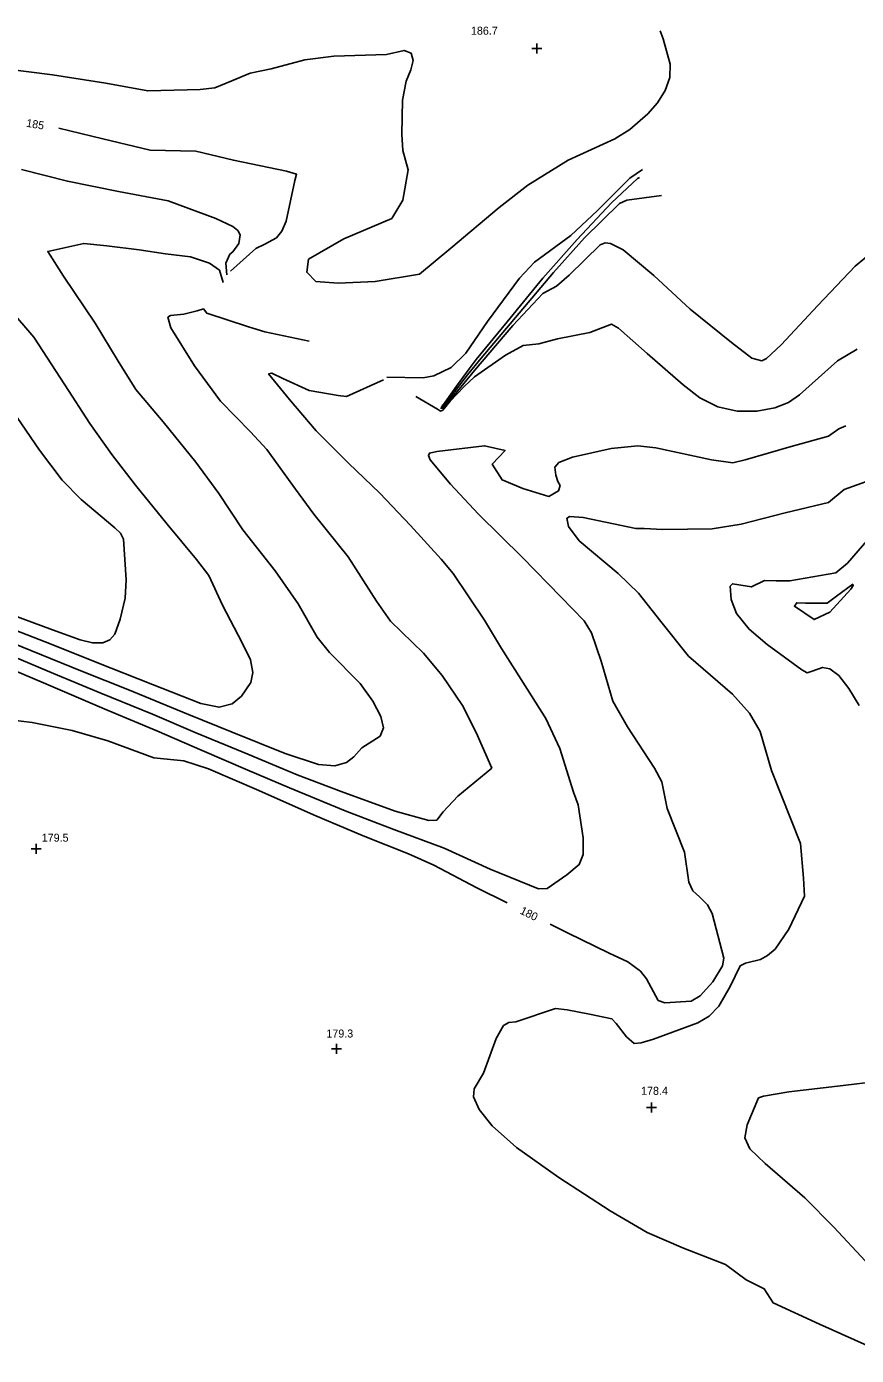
# Model space of a CAD drawing. Extents: x 1467615 to 2003689, y 770235 to 1108726.
# Drawn here: x 1995497.6 to 1995704.8, y 776648.4 to 776980.5 of the extents above; entities that cross this region are included whole.
import ezdxf

# ---------------------------------------------------------------- set-up
doc = ezdxf.new("R2010")
doc.units = 0
for name, color, linetype in [('RD_DTM_Major1', 7, 'Continuous'), ('RD_DTM_Major1_Lbl', 7, 'Continuous'), ('RD_DTM_Minor1', 7, 'Continuous'), ('RD_DTM_Spot_Elev', 7, 'Continuous')]:
    doc.layers.add(name, color=color, linetype=linetype)

msp = doc.modelspace()

# ---------------------------------------------------------------- linework, layer by layer
at = {"layer": 'RD_DTM_Major1'}
for points in [[(1995505.62, 776955.03), (1995516.64, 776952.44), (1995528.45, 776949.54), (1995539.83, 776949.31), (1995549.23, 776947.05), (1995562.51, 776944.31), (1995565.01, 776943.54), (1995564.56, 776941.97), (1995562.4, 776931.84), (1995561.34, 776929.34), (1995560.01, 776927.68), (1995557.09, 776926.11), (1995554.83, 776925.01), (1995548.53, 776919.38)], [(1995587.54, 776892.89), (1995596.57, 776892.69), (1995599.25, 776893.15), (1995603.56, 776895.3), (1995607.22, 776898.86), (1995612.71, 776906.79), (1995620.69, 776917.61), (1995624.37, 776921.59), (1995633.48, 776928.28), (1995640.15, 776934.53), (1995648.22, 776942.59), (1995651.36, 776944.75)], [(1995491.5, 776834.36), (1995504.07, 776829.72), (1995511, 776827.24), (1995514.08, 776826.51), (1995516.6, 776826.45), (1995518.41, 776827.24), (1995519.62, 776828.67), (1995520.98, 776832.36), (1995522.19, 776837.67), (1995522.44, 776842.21), (1995521.79, 776852.42), (1995521.05, 776853.86), (1995519.63, 776855.21), (1995511.26, 776862.3), (1995506.52, 776867.11), (1995500.84, 776874.64), (1995492.92, 776886.19)], [(1995628.33, 776756.19), (1995632.67, 776754.04), (1995643.07, 776748.94), (1995647.72, 776746.78), (1995650.86, 776744.41), (1995652.35, 776742.56), (1995655.29, 776737.13), (1995656.96, 776736.52), (1995663.55, 776736.92), (1995665.73, 776738.32), (1995668.9, 776741.82), (1995671.36, 776745.75), (1995671.63, 776747.72), (1995668.75, 776758.89), (1995667.62, 776761.04), (1995665.62, 776763.01), (1995663.9, 776764.54), (1995662.9, 776766.7), (1995661.89, 776774.2), (1995657.54, 776785.08), (1995656.23, 776791.74), (1995654.37, 776795.14), (1995647.65, 776805.47), (1995643.94, 776811.92), (1995641.07, 776821.9), (1995638.62, 776828.98), (1995636.77, 776831.95), (1995630.99, 776837.96), (1995621.42, 776847.8), (1995610.46, 776858.63), (1995603.39, 776866.15), (1995598.36, 776872.21), (1995597.92, 776873.3), (1995598.18, 776873.88), (1995600.04, 776874.26), (1995611.92, 776875.73), (1995617.06, 776874.55), (1995613.86, 776871.13), (1995616.34, 776867.19), (1995621.53, 776865.06), (1995628.01, 776863.06), (1995630.42, 776864.44), (1995630.77, 776865.82), (1995630.22, 776866.76), (1995629.75, 776868.34), (1995629.45, 776870.41), (1995630.49, 776871.51), (1995633.92, 776872.83), (1995643.5, 776875.02), (1995650.19, 776875.71), (1995654.7, 776875.19), (1995668.59, 776872.17), (1995673.88, 776871.43), (1995677.01, 776872.22), (1995688.48, 776875.54), (1995697.81, 776878.08), (1995700.36, 776879.91), (1995702.09, 776880.73)], [(1995490.64, 776807.61), (1995498.98, 776806.58), (1995508.95, 776804.55), (1995517.88, 776802), (1995529.33, 776797.78), (1995536.88, 776796.97), (1995543.04, 776794.98), (1995555.57, 776789.56), (1995569.26, 776783.52), (1995581.65, 776778.27), (1995592.92, 776773.74), (1995599.27, 776770.93), (1995610.02, 776765.24), (1995617.58, 776761.51)]]:
    msp.add_lwpolyline(points, dxfattribs=at)
at = {"layer": 'RD_DTM_Minor1'}
for points in [[(1995492.96, 776969.77), (1995504.07, 776968.43), (1995517.38, 776966.31), (1995527.86, 776964.36), (1995540.9, 776964.7), (1995544.57, 776965.11), (1995548.84, 776966.89), (1995553.42, 776968.82), (1995558.64, 776969.89), (1995567.1, 776972.16), (1995574.3, 776973.03), (1995587.42, 776973.48), (1995591.85, 776974.51), (1995593.6, 776973.8), (1995594.13, 776971.95), (1995593.53, 776969.68), (1995592.34, 776966.78), (1995591.49, 776962.1), (1995591.28, 776953.58), (1995591.54, 776949.46), (1995592.88, 776944.67), (1995591.54, 776937.08), (1995588.77, 776932.47), (1995576.77, 776927.39), (1995568, 776922.31), (1995567.54, 776919.08), (1995569.84, 776916.77), (1995575.38, 776916.31), (1995584.62, 776916.77), (1995595.7, 776918.62), (1995603.55, 776925.08), (1995615.55, 776935.24), (1995622.71, 776940.79), (1995632.78, 776947.07), (1995644.46, 776952.37), (1995648.24, 776954.7), (1995652.73, 776958.69), (1995655.1, 776961.42), (1995657.06, 776964.48), (1995658.2, 776967.75), (1995658.28, 776971.07), (1995656.49, 776977.36), (1995655.8, 776979.36)], [(1995496.32, 776944.75), (1995507.81, 776941.79), (1995520.57, 776939.21), (1995532.97, 776936.9), (1995544.83, 776932.48), (1995549.06, 776930.54), (1995550.37, 776929.5), (1995550.95, 776928.38), (1995550.63, 776926.23), (1995549.12, 776924.21), (1995548.32, 776923.58), (1995547.33, 776921.38), (1995547.62, 776918.4)], [(1995601.28, 776885.7), (1995601.59, 776885.95), (1995602.1, 776886.57), (1995604.95, 776890.61), (1995608.1, 776894.95), (1995609.87, 776897.27), (1995617.58, 776906.65), (1995626.51, 776917.62), (1995635.07, 776927.27), (1995643.59, 776936.42), (1995650.13, 776942.47), (1995650.58, 776942.78)], [(1995601.12, 776885.4), (1995601.65, 776885.62), (1995602.13, 776886.16), (1995604.44, 776889.22), (1995607.68, 776893.43), (1995611.1, 776897.62), (1995620.58, 776908.82), (1995629.13, 776919.02), (1995636.92, 776927.67), (1995645.66, 776936.23), (1995647.46, 776937.08), (1995656.09, 776938.24)], [(1995491.52, 776827.48), (1995503.57, 776822.53), (1995511.56, 776819.34), (1995522.86, 776814.83), (1995538.05, 776808.58), (1995548.91, 776804.17), (1995562.15, 776798.83), (1995570.45, 776796.07), (1995574.58, 776795.73), (1995577.51, 776796.59), (1995579.27, 776798.01), (1995581.33, 776800.26), (1995585.9, 776803.17), (1995586.72, 776805.22), (1995586.05, 776808.09), (1995584.06, 776811.94), (1995580.87, 776816.3), (1995573.21, 776824.1), (1995570.17, 776827.91), (1995565.43, 776836.24), (1995559.65, 776844.48), (1995551.6, 776854.71), (1995545.61, 776863.83), (1995539.83, 776871.65), (1995531.7, 776881.73), (1995524.86, 776889.8), (1995520.5, 776896.85), (1995514.73, 776906.31), (1995506.82, 776918.08), (1995502.89, 776924.27), (1995511.87, 776926.28), (1995517.66, 776925.64), (1995525.74, 776924.7), (1995532.28, 776923.69), (1995538.51, 776922.94), (1995543.26, 776921.32), (1995545.77, 776919.55), (1995546.71, 776916.54)], [(1995600.96, 776885.07), (1995601.35, 776885.12), (1995601.68, 776885.27), (1995603.11, 776886.87), (1995606.79, 776891.3), (1995609.39, 776894.52), (1995619.03, 776905.75), (1995626.51, 776913.73), (1995629.86, 776915.59), (1995633.04, 776918.38), (1995640.76, 776925.95), (1995642.04, 776926.38), (1995643.4, 776926.29), (1995646.51, 776924.66), (1995654.19, 776918.24), (1995663.29, 776909.81), (1995673.57, 776901.48), (1995678.66, 776897.58), (1995681.13, 776896.92), (1995682.35, 776897.48), (1995685.97, 776900.9), (1995695.17, 776910.77), (1995704.49, 776920.57), (1995711.72, 776926.6)], [(1995491.74, 776830.78), (1995503.76, 776826.11), (1995515.18, 776821.58), (1995529.07, 776816.06), (1995541.14, 776811.29), (1995545.65, 776810.38), (1995548.96, 776811.2), (1995551.23, 776813.15), (1995553.55, 776816.56), (1995554.08, 776819.1), (1995553.47, 776822.22), (1995551.45, 776826.51), (1995546.48, 776835.88), (1995543.14, 776843.31), (1995540.06, 776847.32), (1995532.73, 776856.11), (1995524.78, 776865.87), (1995518.88, 776873.53), (1995513.43, 776881.32), (1995507.13, 776890.98), (1995499.41, 776902.88), (1995493.3, 776909.92)], [(1995494.68, 776822.86), (1995504.31, 776818.8), (1995516.17, 776813.88), (1995529.05, 776808.65), (1995539.73, 776804.08), (1995552.83, 776798.65), (1995565.19, 776793.49), (1995576.11, 776789.3), (1995589.6, 776784.44), (1995598.06, 776782.11), (1995600, 776782.18), (1995601.61, 776784.29), (1995605.23, 776788.13), (1995613.73, 776795.2), (1995609.85, 776804.07), (1995606.39, 776810.82), (1995601.31, 776818.35), (1995596.7, 776823.86), (1995588.44, 776831.89), (1995584.99, 776836.85), (1995577.89, 776847.94), (1995569.32, 776858.66), (1995564.71, 776864.9), (1995557.55, 776874.8), (1995553.52, 776879.21), (1995546.03, 776886.83), (1995539.55, 776895.66), (1995533.62, 776905.22), (1995532.87, 776907.81), (1995533.57, 776908.3), (1995536.88, 776908.63), (1995540.17, 776909.47), (1995541.74, 776909.89), (1995542.58, 776908.81), (1995553.01, 776905.46), (1995557.12, 776904.15), (1995568.14, 776901.81)], [(1995594.81, 776888.02), (1995600.17, 776884.85), (1995600.94, 776884.38), (1995601.5, 776884.61), (1995603.34, 776886.87), (1995606.88, 776890.52), (1995609.41, 776892.98), (1995617.17, 776898.39), (1995621.61, 776900.76), (1995625.45, 776901.19), (1995630.17, 776902.47), (1995638.25, 776904.02), (1995643.59, 776906.09), (1995645.34, 776905.06), (1995652.57, 776898.79), (1995661.52, 776890.9), (1995665.7, 776887.69), (1995670.16, 776885.48), (1995675.02, 776884.39), (1995679.91, 776884.36), (1995684.36, 776885.17), (1995687.8, 776886.51), (1995690.56, 776888.42), (1995700.02, 776896.93), (1995704.93, 776899.87)], [(1995492.01, 776820.64), (1995501.83, 776816.51), (1995517.01, 776810.02), (1995530.12, 776804.52), (1995541.41, 776799.58), (1995552.84, 776794.7), (1995563.22, 776790.23), (1995577.12, 776784.49), (1995589.25, 776779.85), (1995601.82, 776775.2), (1995613.35, 776769.94), (1995625.44, 776765.01), (1995627.56, 776765.08), (1995632.47, 776768.53), (1995635.58, 776771.06), (1995636.58, 776773.62), (1995636.55, 776777.78), (1995635.34, 776786), (1995634.13, 776789.21), (1995630.73, 776800.08), (1995627.21, 776807.59), (1995621.07, 776817.35), (1995616.18, 776825.07), (1995611.9, 776832.11), (1995604.1, 776843.79), (1995601.1, 776847.39), (1995593.43, 776855.82), (1995585.78, 776863.84), (1995577.93, 776871.37), (1995569.92, 776879.44), (1995563.26, 776887.25), (1995558.03, 776893.65), (1995558.8, 776893.89), (1995561.6, 776892.5), (1995568.15, 776889.55), (1995575.38, 776888.29), (1995577.51, 776888.04), (1995586.74, 776892.18)], [(1995712.99, 776648.44), (1995695.53, 776656.21), (1995683.95, 776661.55), (1995681.74, 776665.11), (1995677.25, 776667.3), (1995672.06, 776671.14), (1995661.62, 776675.2), (1995652.49, 776679.12), (1995643.31, 776684.6), (1995630.46, 776692.88), (1995619.88, 776700.42), (1995613.82, 776705.82), (1995610.6, 776709.89), (1995609.2, 776713.01), (1995609.32, 776715.08), (1995611.7, 776718.96), (1995614.86, 776727.65), (1995616.68, 776730.84), (1995617.98, 776731.59), (1995619.78, 776731.8), (1995629.61, 776735.1), (1995632.57, 776734.78), (1995638.12, 776733.68), (1995643.74, 776732.54), (1995644.83, 776731.41), (1995647.39, 776728.04), (1995649.27, 776726.4), (1995651.07, 776726.52), (1995654.15, 776727.47), (1995665.21, 776731.5), (1995668, 776733.22), (1995670.41, 776735.74), (1995673.29, 776740.61), (1995675.76, 776745.8), (1995677.11, 776746.46), (1995680.79, 776747.39), (1995682.6, 776748.35), (1995684.48, 776749.94), (1995687.93, 776754.95), (1995691.81, 776763.19), (1995691.58, 776767.65), (1995690.8, 776776.34), (1995688.39, 776782.42), (1995683.53, 776794.56), (1995680.77, 776804.3), (1995678.04, 776808.94), (1995673.82, 776813.68), (1995662.87, 776823.14), (1995655.9, 776831.79), (1995650.33, 776838.89), (1995645.25, 776843.78), (1995635.54, 776851.99), (1995632.92, 776855.51), (1995632.51, 776857.61), (1995633.23, 776858.02), (1995636.59, 776857.82), (1995649.69, 776855.08), (1995651.77, 776855.04), (1995656.42, 776854.83), (1995668.73, 776854.93), (1995675.99, 776856.1), (1995687.01, 776858.92), (1995697.77, 776861.54), (1995701.72, 776864.83), (1995708.23, 776867.16)], [(1995705.44, 776810.83), (1995702.87, 776815.06), (1995700.37, 776818.29), (1995698.16, 776819.95), (1995696.31, 776820.34), (1995693.72, 776819.43), (1995692.44, 776819.02), (1995691.15, 776819.77), (1995682.5, 776826.09), (1995677.99, 776829.86), (1995674.86, 776833.81), (1995673.5, 776837.33), (1995673.27, 776840.67), (1995673.85, 776841.26), (1995678.54, 776840.46), (1995681.78, 776842.02), (1995684.72, 776841.93), (1995688.13, 776841.93), (1995699.62, 776843.96), (1995702.51, 776846.39), (1995708.94, 776853.83)], [(1995698.1, 776834.16), (1995694.23, 776832.28), (1995689.3, 776835.6), (1995689.88, 776836.5), (1995692.02, 776836.42), (1995697.5, 776836.35), (1995699.83, 776838.15), (1995703.87, 776841.11), (1995703.98, 776840.83), (1995703.4, 776839.89), (1995698.1, 776834.16)], [(1995707.05, 776671.95), (1995699.17, 776680.52), (1995691.89, 776687.84), (1995682, 776696.43), (1995678.13, 776700.07), (1995676.89, 776702.78), (1995677.48, 776706.03), (1995680.35, 776712.76), (1995681.59, 776713.18), (1995687.93, 776714.29), (1995700.03, 776715.69), (1995711.1, 776717.03)]]:
    msp.add_lwpolyline(points, dxfattribs=at)
at = {"layer": 'RD_DTM_Spot_Elev'}
for p, q in [((1995625, 776973.75), (1995625, 776976.25)), ((1995623.75, 776975), (1995626.25, 776975)), ((1995500, 776773.75), (1995500, 776776.25)), ((1995498.75, 776775), (1995501.25, 776775)), ((1995575, 776723.75), (1995575, 776726.25)), ((1995573.75, 776725), (1995576.25, 776725)), ((1995652.33, 776710.42), (1995654.83, 776710.42)), ((1995653.58, 776709.17), (1995653.58, 776711.67))]:
    msp.add_line(p, q, dxfattribs=at)

# ---------------------------------------------------------------- texts
at = {"layer": 'RD_DTM_Major1_Lbl'}
for s, rotation, p in [('185', 350.6513, (1995497.41, 776955.43)), ('180', 333.6136, (1995620.6, 776758.91))]:
    msp.add_text(s, height=2, rotation=rotation, dxfattribs=at).set_placement(p)
at = {"layer": 'RD_DTM_Spot_Elev'}
for s, p in [('186.7', (1995608.54, 776978.42)), ('179.5', (1995501.39, 776776.8)), ('179.3', (1995572.45, 776727.87)), ('178.4', (1995651.01, 776713.55))]:
    msp.add_text(s, height=2, dxfattribs=at).set_placement(p)

doc.saveas('drawing.dxf')
